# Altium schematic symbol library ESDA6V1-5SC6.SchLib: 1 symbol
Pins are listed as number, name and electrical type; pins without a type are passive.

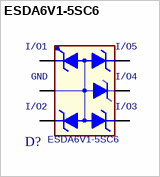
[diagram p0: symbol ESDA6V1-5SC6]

## ESDA6V1-5SC6
designator D?
footprint ST_SOT23-6L
pins: 1 I/O1, 2 GND, 3 I/O2, 4 I/O3, 5 I/O4, 6 I/O5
